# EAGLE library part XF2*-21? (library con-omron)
OMRON FPC Connector Source : http://www.omron.com/ecb/products/pdf/fpc.pdf
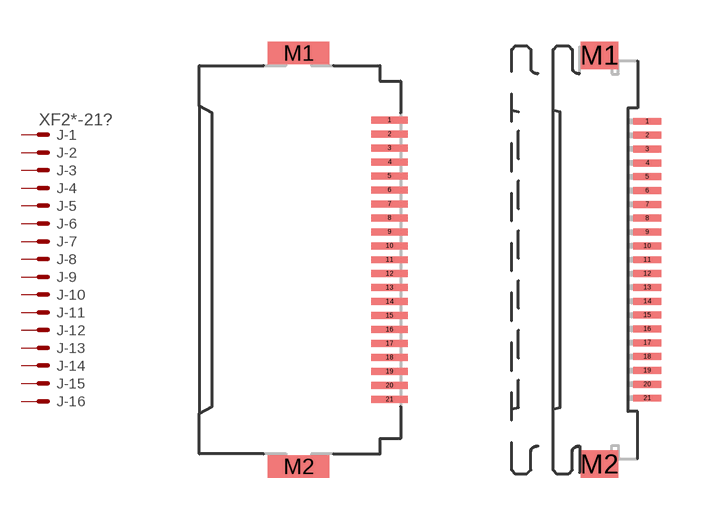
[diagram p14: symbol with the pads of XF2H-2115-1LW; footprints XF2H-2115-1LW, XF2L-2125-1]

Designator prefix J; gates -1=PV -2=P -3=P -4=P -5=P -6=P -7=P -8=P -9=P -10=P -11=P -12=P -13=P -14=P -15=P -16=P -17=P -18=P -19=P -20=P -21=P

## XF2H-2115-1LW (OC_FARNELL: unknown; OC_NEWARK: unknown)  [XF2H-2115-1LW]
1  -1:MSV  pas
2  -2:MS  pas
3  -3:MS  pas
4  -4:MS  pas
5  -5:MS  pas
6  -6:MS  pas
7  -7:MS  pas
8  -8:MS  pas
9  -9:MS  pas
10  -10:MS  pas
11  -11:MS  pas
12  -12:MS  pas
13  -13:MS  pas
14  -14:MS  pas
15  -15:MS  pas
16  -16:MS  pas
17  -17:MS  pas
18  -18:MS  pas
19  -19:MS  pas
20  -20:MS  pas
21  -21:MS  pas

## XF2L-2125-1 (MPN: XF2L-2125-1; OC_FARNELL: unknown; OC_NEWARK: 37M0895)  [XF2L-2125-1]
Pads as for XF2H-2115-1LW

## XF2N-2115-3 (MPN: XF2N-2115-3; OC_FARNELL: unknown; OC_NEWARK: 37M0941)  [XF2N-2115-3]
Pads as for XF2H-2115-1LW

## XF2C-2155-41A (MPN: XF2C-2155-41A; OC_FARNELL: unknown; OC_NEWARK: 78M3583)  [XF2C-2155-41A]
Pads as for XF2H-2115-1LW

## Footprint XF2H-2115-1LW (pad centres in mm)
Standard Rotary Backlock Type (0.5 mm-pitch) Source : http://www.omron.com/ecb/products/pdf/fpc.pdf
smd 1.3 x 0.25: 1 3.175,5; 2 3.175,4.5; 3 3.175,4; 4 3.175,3.5; 5 3.175,3; 6 3.175,2.5; 7 3.175,2; 8 3.175,1.5; 9 3.175,1; 10 3.175,0.5; 11 3.175,0; 12 3.175,-0.5; 13 3.175,-1; 14 3.175,-1.5; 15 3.175,-2; 16 3.175,-2.5; 17 3.175,-3; 18 3.175,-3.5; 19 3.175,-4; 20 3.175,-4.5; 21 3.175,-5
smd 2.2 x 0.8: M1 -0.075,7.4; M2 -0.075,-7.4

## Footprint XF2L-2125-1 (pad centres in mm)
ZIF Slide-locking Type (0.5 mm-pitch) Upper-contact Type Source : http://www.omron.com/ecb/products/pdf/fpc.pdf
smd 1 x 0.25: 1 1.905,5; 2 1.905,4.5; 3 1.905,4; 4 1.905,3.5; 5 1.905,3; 6 1.905,2.5; 7 1.905,2; 8 1.905,1.5; 9 1.905,1; 10 1.905,0.5; 11 1.905,0; 12 1.905,-0.5; 13 1.905,-1; 14 1.905,-1.5; 15 1.905,-2; 16 1.905,-2.5; 17 1.905,-3; 18 1.905,-3.5; 19 1.905,-4; 20 1.905,-4.5; 21 1.905,-5
smd 1.34 x 1: M1 0.18,7.388; M2 0.18,-7.388

## Footprint XF2N-2115-3 (pad centres in mm)
Low-profile Rotary Backlock Type (0.5 mm-pitch) Source : http://www.omron.com/ecb/products/pdf/fpc.pdf
smd 1 x 0.25: 1 2.54,5; 2 2.54,4.5; 3 2.54,4; 4 2.54,3.5; 5 2.54,3; 6 2.54,2.5; 7 2.54,2; 8 2.54,1.5; 9 2.54,1; 10 2.54,0.5; 11 2.54,0; 12 2.54,-0.5; 13 2.54,-1; 14 2.54,-1.5; 15 2.54,-2; 16 2.54,-2.5; 17 2.54,-3; 18 2.54,-3.5; 19 2.54,-4; 20 2.54,-4.5; 21 2.54,-5
smd 1.4 x 1: M1 -0.61,6.4; M2 -0.61,-6.4

## Footprint XF2C-2155-41A (pad centres in mm)
Low-profile Rotary Backlock Type (0.3 mm-pitch) Source : http://www.omron.com/ecb/products/pdf/fpc.pdf
smd 0.6 x 0.26: 1 -1.8,3; 3 -1.8,2.4; 5 -1.8,1.8; 7 -1.8,1.2; 9 -1.8,0.6; 11 -1.8,0; 13 -1.8,-0.6; 15 -1.8,-1.2; 17 -1.8,-1.8; 19 -1.8,-2.4; 21 -1.8,-3
smd 0.9 x 0.25: 2 1.65,2.7; 4 1.65,2.1; 6 1.65,1.5; 8 1.65,0.9; 10 1.65,0.3; 12 1.65,-0.3; 14 1.65,-0.9; 16 1.65,-1.5; 18 1.65,-2.1; 20 1.65,-2.7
